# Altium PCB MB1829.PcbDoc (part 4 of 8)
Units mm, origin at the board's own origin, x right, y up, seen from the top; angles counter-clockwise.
Board outline 90 x 110 mm, 6 copper layers (Top Layer, Signal Layer 1, Signal Layer 2, Signal Layer 3, Signal Layer 4, Bottom Layer), stack 1.578 mm thick; 466 components, 354 nets, 2058 pads, 1522 vias.
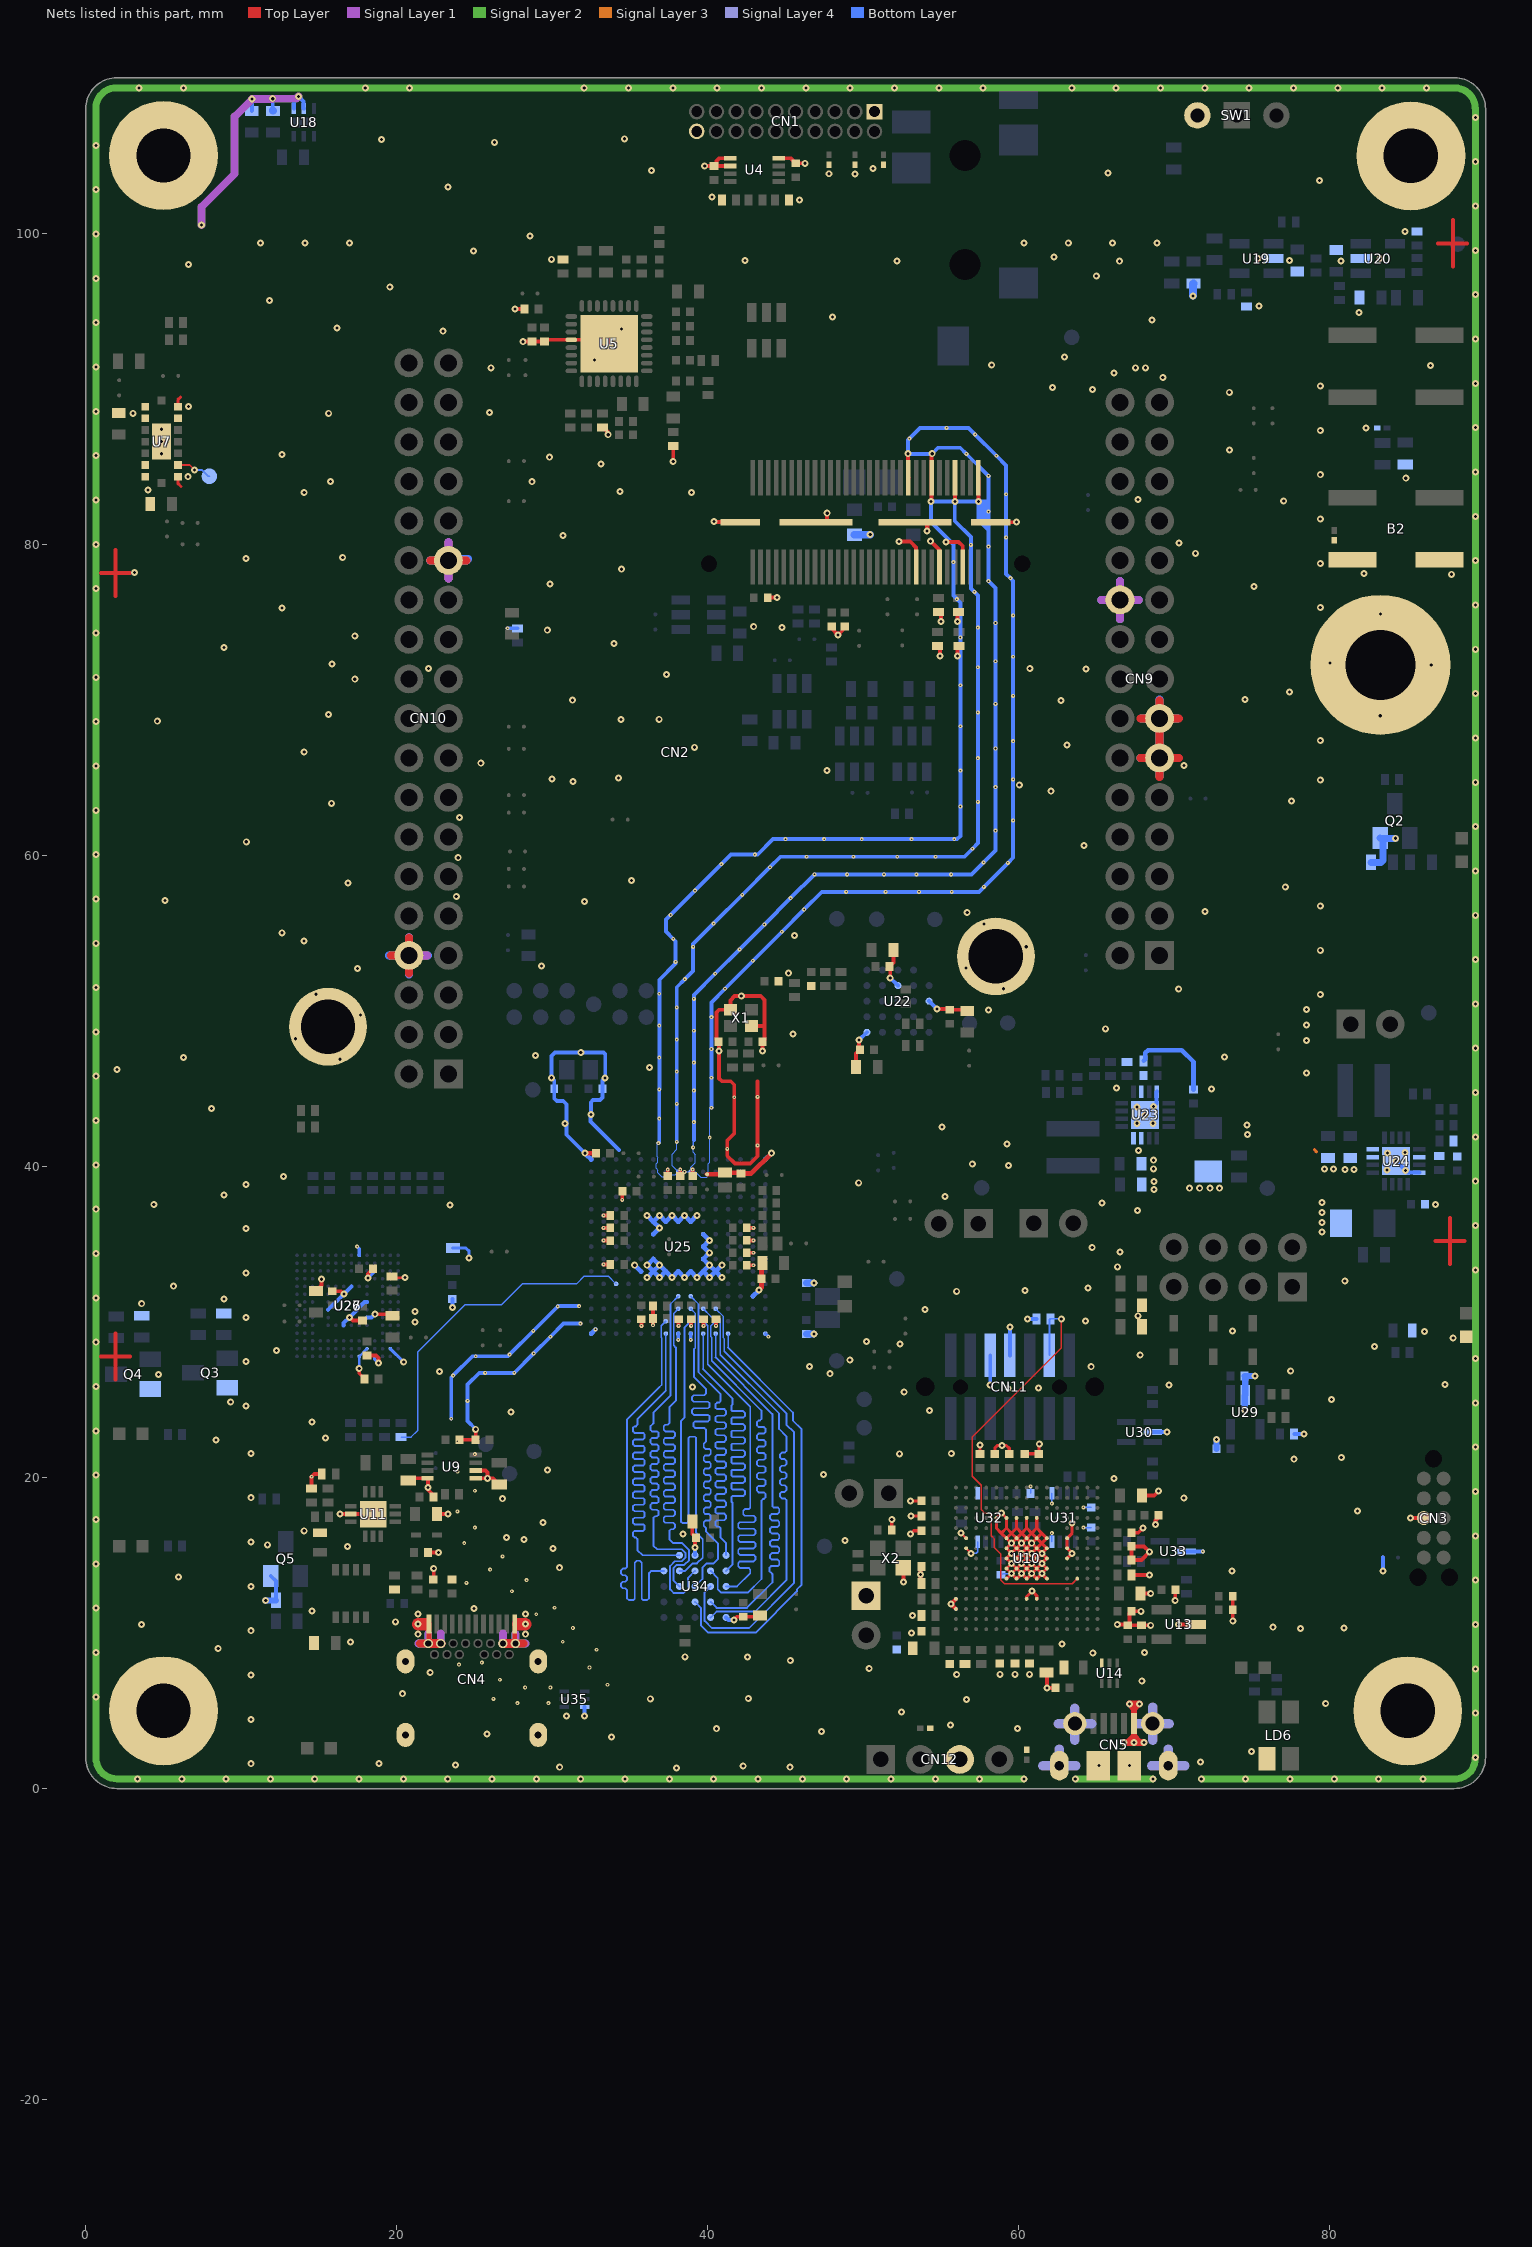
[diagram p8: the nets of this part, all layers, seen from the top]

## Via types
v1: diameter 0.45, hole 0.2, Top Layer to Bottom Layer, tented both sides, 1062 vias
v2: diameter 0.25, hole 0.1, Signal Layer 4 to Bottom Layer, tented both sides, 274 vias
v3: diameter 0.25, hole 0.1, Signal Layer 3 to Signal Layer 4, tented both sides, 119 vias
v4: diameter 0.25, hole 0.1, Top Layer to Signal Layer 1, tented both sides, 47 vias
v5: diameter 0.25, hole 0.1, Signal Layer 1 to Signal Layer 2, tented both sides, 20 vias

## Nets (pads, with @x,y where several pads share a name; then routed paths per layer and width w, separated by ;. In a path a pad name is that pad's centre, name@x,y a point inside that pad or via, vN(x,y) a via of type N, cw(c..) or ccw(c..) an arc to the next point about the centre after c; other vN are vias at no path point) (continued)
eMMC_RSTn: R111.1 U25.C11 | length 21.3
  Bottom Layer w0.1: R111.1@20.275,22.6 20.916,22.6 21.36,23.044 21.36,28.08 24.38,31.1 26.725,31.1 28.075,32.45 31.55,32.45 32.05,32.95 33.6,32.95 U25.C11@34.1,32.45
GND: B2.3 B2.4 C1.1 C2.2 C8.2 C11.1 C12.1 C18.2 C21.1 C22.1 C23.1 C24.1 C26.1 C27.1 C28.1 C29.1 C30.1 C31.1 C32.2 C33.2 C34.1 C35.1 C36.1 C37.1 C38.1 C39.1 C40.1 C42.1 C44.1 C46.1 C47.1 C49.1 C50.1 C51.1 C52.1 C53.1 C54.1 C55.1 C56.1 C57.1 C58.1 C59.1 C60.1 C61.1 C62.1 C63.1 C64.1 C65.1 C66.1 C67.1 C68.1 C69.1 C70.1 C71.1 C72.2 C73.2 C74.2 C75.2 C76.2 C77.2 C78.1 C79.1 C80.2 C81.1 C82.1 C83.2 C84.1 C85.2 C86.2 C87.2 C88.1 C89.2 C90.1 C91.2 C92.2 C93.1 C94.1 C95.1 C96.1 C97.1 C98.1 C99.1 C100.1 C101.2 C102.1 C103.1 C104.2 C105.2 C106.1 C107.2 C108.2 C109.2 C110.1 C111.1 C112.1 C113.2 C114.1 C115.1 C116.1 C117.1 C118.1 C126.1 C127.2 C128.2 C129.1 C130.1 C131.2 C132.1 C133.1 C134.1 C135.1 C136.1 C137.1 C138.1 C139.1 C140.1 C141.1 C142.1 C143.2 C144.2 C145.1 C146.1 C148.2 C149.1 CN1.1 CN1.20 CN2.1 CN2.6 CN2.7 CN2.12 CN2.13 CN2.18 CN2.19 CN2.61 CN2.62 CN2.63 CN2.64 CN2.PTH2 CN3.3 CN4.A1 CN4.A12 CN4.B1 CN4.B12 CN4.SH1 CN4.SH2 CN4.SH3 CN4.SH4 CN5.5 CN5.6 CN5.7 CN5.8 CN5.9 CN5.10 CN5.11 CN9.11 CN9.13 CN9.20 CN10.8 CN10.27 CN11.5 CN11.7 CN12.3 H1.1 H2.1 H3.1 H4.PTH1 H5.PTH1 H6.1 H7.1 JP6.1 L1.1 L5.1 LD2.2 LD6.3 Q2.2 Q3.2 Q4.2 Q5.2 R1.1 R3.1 R5.1 R12.2 R15.2 R16.2 R17.2 R18.2 R19.2 R30.1 R32.1 R35.1 R37.2 R38.1 R39.1 R46.1 R47.2 R49.1 R51.2 R53.1 R58.1 R64.1 R67.1 R71.1 R80.1 R81.1 R82.1 R91.1 R93.1 R104.1 R106.1 R108.1 R115.1 R128.1 SB30.1 SB61.1 SW1.3 U1.2 U2.2 U3.2 U4.4 U4.5 U4.6 U5.28 U5.33 U7.A1 U7.A2 U7.A6 U7.A7 U7.B4 U7.C1 U7.C6 U7.C7 U8.2 U9.4 U9.5 U9.6 U10.D5 U10.D6 U10.D7 U10.D8 U10.D9 U10.F2 U10.F6 U10.F7 U10.F8 U10.F9 U10.F10 U10.F12 U10.G2 U10.G6 U10.G7 U10.G8 U10.G9 U10.G10 U10.G12 U10.H6 U10.H7 U10.H8 U10.H9 U10.H10 U10.H12 U10.J6 U10.J7 U10.J8 U10.J9 U10.J10 U10.K6 U10.K7 U10.K8 U10.K9 U10.K10 U10.M1 U10.M8 U10.M9 U10.N1 U11.2 U11.13 U12.2 U13.2 U14.3 U15.2 U16.2 U17.2 U18.4 U18.5 U19.2 U20.2 U21.2 U22.B3 U22.C1 U22.E5 U23.6 U23.8 U23.15 U23.16 U23.17 U24.6 U24.8 U24.15 U24.16 U24.17 U25.A1 U25.A15 U25.E10 U25.F6 U25.F7 U25.F9 U25.F10 U25.G6 U25.G10 U25.H2 U25.H6 U25.H10 U25.H15 U25.J2 U25.J6 U25.J10 U25.J15 U25.K7 U25.K8 U25.K9 U25.K10 U25.L10 U25.P12 U25.R1 U25.R15 U26.A6 U26.C4 U26.E7 U26.G5 U26.H10 U26.J5 U26.K8 U26.N2 U26.N5 U26.P4 U26.P6 U27.A6 U27.C4 U27.E7 U27.G5 U27.H10 U27.J5 U27.K8 U27.N2 U27.N5 U27.P4 U27.P6 U28.2 U29.2 U30.2 U31.4 U31.5 U32.4 U32.5 U33.2 U34.C1 U34.E5 U35.3 X1.2 X1.4 X2.2 | length 1127.3
  Top Layer w0.15: R30.1@19.7,32.925 19.775,32.85 v1(20.525,32.85) ; U10.G2@56.6,15.45 v1(56.925,15.125)
  Top Layer w0.153: v1(56.275,16.425) U10.F2@56.6,16.1
  Top Layer w0.2: U7.C1@5.925,84.35 5.925,83.919 6.128,83.716 ; U7.C7@5.925,88.85 5.925,89.288 6.107,89.47 ; v1(17.585,27) 17.585,26.685 C70.1@17.933,26.338 ; v1(53.025,16.375) 53.225,16.575 C86.2@53.75,16.575 ; v1(53.025,18.5) C80.2@53.725,18.5 ; v1(53.05,17.525) C83.2@53.75,17.525 ; C75.2@57.5,21.525 v1(57.5,22.1) ; C76.2@58.45,21.525 58.45,21.9 58.6,22.05 v1(58.9,22.05) 59.205,22.05 59.375,21.88 C77.2@59.375,21.525 ; U10.K6@59.2,13.5 v1(59.525,13.825) ; U10.D7@59.85,17.4 59.85,16.75 ; C73.2@60.375,21.525 C74.2@61.275,21.525 61.293,21.543 61.293,22.133 v1(61.31,22.15) ; U10.M8@60.5,12.2 60.5,12.35 v1(60.85,12.7) 61.15,12.4 U10.M9@61.15,12.2 ; U10.D8@60.5,17.4 60.5,16.75 ; v1(60.825,15.125) U10.H9@61.15,14.8 ; U10.D9@61.15,17.4 61.15,16.75 ; U10.K10@61.8,13.5 v1(61.475,13.825) ; U10.F10@61.8,16.1 61.475,16.425 ; U10.F10@61.8,16.1 61.475,15.775 ; U10.H12@63.1,14.8 v1(63.425,15.125) U10.G12@63.1,15.45 U10.F12@63.1,16.1 63.425,16.425 v1(63.425,17.075) ; 58.875,16.425 58.55,16.75 U10.D5@58.55,17.4 v1(58.875,17.725) U10.D6@59.2,17.4 59.2,16.75 ; 58.875,16.425 U10.F6@59.2,16.1 ; 58.875,16.425 59.2,16.75 ; U10.F6@59.2,16.1 59.525,16.425 ; U10.F6@59.2,16.1 v1(59.525,15.775) ; 59.2,16.75 59.525,16.425 ; v1(59.525,13.825) U10.J7@59.85,14.15 ; v1(59.525,13.825) U10.K7@59.85,13.5 v1(60.175,13.825) ; v1(59.525,13.825) U10.J6@59.2,14.15 v1(59.525,14.475) ; v1(59.525,14.475) U10.H7@59.85,14.8 ; v1(59.525,14.475) U10.J7@59.85,14.15 ; v1(59.525,14.475) U10.H6@59.2,14.8 v1(59.525,15.125) ; v1(59.525,15.125) U10.G7@59.85,15.45 v1(60.175,15.125) ; v1(59.525,15.125) U10.G6@59.2,15.45 v1(59.525,15.775) ; v1(59.525,15.125) 59.532,15.125 59.85,14.807 U10.H7@59.85,14.8 ; v1(59.525,15.775) 59.714,15.586 U10.G7@59.85,15.45 v1(60.175,15.775) ; v1(59.525,15.775) U10.F7@59.85,16.1 ; 59.525,16.425 59.85,16.75 ; 59.525,16.425 U10.F7@59.85,16.1 ; U10.J7@59.85,14.15 v1(60.175,14.475) ; U10.J7@59.85,14.15 v1(60.175,13.825) ; U10.H7@59.85,14.8 v1(60.175,15.125) ; U10.H7@59.85,14.8 v1(60.175,14.475) ; U10.F7@59.85,16.1 60.175,16.425 ; U10.F7@59.85,16.1 59.993,15.957 v1(60.175,15.775) ; 59.85,16.75 60.175,16.425 ; v1(60.175,13.825) U10.K8@60.5,13.5 v1(60.825,13.825) ; v1(60.175,13.825) U10.J8@60.5,14.15 ; v1(60.175,14.475) U10.J8@60.5,14.15 ; v1(60.175,14.475) U10.H8@60.5,14.8 ; v1(60.175,15.125) U10.H8@60.5,14.8 ; v1(60.175,15.125) U10.G8@60.5,15.45 ; v1(60.175,15.775) U10.G8@60.5,15.45 ; v1(60.175,15.775) U10.F8@60.5,16.1 ; 60.175,16.425 60.5,16.75 ; 60.175,16.425 U10.F8@60.5,16.1 ; U10.J8@60.5,14.15 v1(60.825,14.475) ; U10.J8@60.5,14.15 v1(60.825,13.825) ; U10.H8@60.5,14.8 v1(60.825,15.125) ; U10.H8@60.5,14.8 v1(60.825,14.475) ; U10.G8@60.5,15.45 v1(60.825,15.125) ; U10.G8@60.5,15.45 v1(60.825,15.775) ; U10.F8@60.5,16.1 60.8,16.4 ; U10.F8@60.5,16.1 v1(60.825,15.775) ; 60.5,16.75 60.8,16.45 ; 60.8,16.4 60.825,16.425 ; 60.8,16.4 60.8,16.45 ; 60.8,16.45 60.825,16.425 ; v1(60.825,13.825) U10.K9@61.15,13.5 v1(61.475,13.825) ; v1(60.825,13.825) U10.J9@61.15,14.15 ; v1(60.825,14.475) U10.J9@61.15,14.15 ; v1(60.825,14.475) U10.H9@61.15,14.8 ; v1(60.825,15.125) U10.G9@61.15,15.45 ; v1(60.825,15.775) U10.G9@61.15,15.45 ; v1(60.825,15.775) U10.F9@61.15,16.1 ; 60.825,16.425 61.15,16.75 ; 60.825,16.425 U10.F9@61.15,16.1 ; U10.J9@61.15,14.15 v1(61.475,13.825) ; U10.J9@61.15,14.15 v1(61.475,14.475) ; U10.H9@61.15,14.8 v1(61.475,15.125) ; U10.H9@61.15,14.8 v1(61.475,14.475) ; U10.G9@61.15,15.45 v1(61.475,15.125) ; U10.G9@61.15,15.45 61.475,15.775 ; U10.F9@61.15,16.1 61.475,16.425 ; U10.F9@61.15,16.1 61.475,15.775 ; 61.15,16.75 61.475,16.425 ; v1(61.475,13.825) U10.J10@61.8,14.15 v1(61.475,14.475) ; v1(61.475,14.475) U10.H10@61.8,14.8 v1(61.475,15.125) ; v1(61.475,15.125) U10.G10@61.8,15.45 61.475,15.775
  Top Layer w0.25: 0.975,27.775 1.925,27.775 ; 0.975,78.15 1.925,78.15 ; 1.925,26.287 1.925,27.775 ; 1.925,29.275 1.925,27.775 ; 1.925,76.662 1.925,78.15 ; 1.925,79.65 1.925,78.15 ; 2.85,27.775 1.925,27.775 ; 2.85,78.15 1.925,78.15 ; R39.1@14.525,19.3 v4(14.525,20.05) 14.691,20.216 15.166,20.216 R38.1@15.175,20.225 ; C57.1@14.8,32 15.15,32.35 v1(15.15,32.75) ; C58.1@15.85,31.975 16.426,31.975 v1(16.6,31.801) ; v1(16.35,17.65) U11.2@17.05,17.65 U11.13@18.475,17.65 ; v1(16.95,30.3) 16.975,30.3 17.175,30.1 C66.1@17.8,30.1 ; C69.1@18.085,27.836 18.664,27.836 18.825,27.675 v1(18.825,27.375) ; v1@18.15,32.825 18.15,33.1 C55.1@18.475,33.425 ; v1(18.6,30.5) 19.625,30.5 C67.1@19.725,30.4 ; R35.1@20.725,19.8 20.875,19.95 U9.4@21.975,19.95 22,19.925 v1(22,19.35) 22,19.212 C79.1@22.35,18.862 ; C90.1@22,15.175 v1(22.675,15.175) ; C93.1@22.375,13.475 v1(22.375,14.15) ; C81.1@22.575,17.65 v1(23.3,17.65) ; C71.1@24.025,22.425 C72.2@25.075,22.425 v1(25.075,23.1) ; U9.5@25.075,19.95 v1(25.825,19.95) ; U9.6@25.075,20.45 25.7,20.45 25.825,20.325 v1(25.825,19.95) ; R37.2@26.6,19.55 26.2,19.95 v1(25.825,19.95) ; v1(27.6,95.125) C8.2@28.2,95.125 ; v1(28.122,93.025) 28.125,93.025 28.15,93.05 C12.1@29.5,93.05 ; C12.1@29.5,93.15 U5.28@31.225,93.15 33.4,93.15 34.1,93.85 v1(34.45,93.85) ; R12.2@33.225,87.5 33.32,87.5 33.558,87.263 33.558,87.084 v1(33.596,87.046) ; v4(33.3,35.25) C50.1@33.724,35.25 ; v4(33.3,36.05) C46.1@33.724,36.05 ; v4(33.3,36.85) C44.1@33.724,36.85 ; v4(33.3,33.7) C53.1@33.725,33.7 ; v4(34.5,37.85) 34.5,38.375 C42.1@34.525,38.4 ; v4(35.725,29.75) C60.1@35.725,30.175 ; v4(36.475,29.8) C65.1@36.475,31.025 ; C38.1@37.425,39.375 v4(37.425,39.8) ; v1(37.775,85.325) R15.2@37.775,86.325 ; v4(38.125,29.75) C61.1@38.125,30.175 ; C39.1@38.225,39.375 v4(38.225,39.8) ; v4(38.925,29.75) C62.1@38.925,30.175 ; C84.1@39,17.175 39,16.375 C88.1@39.25,16.125 39.175,16.05 v1(39.175,15.5) ; C40.1@39.025,39.375 v4(39.025,39.8) ; v4(39.725,29.75) C63.1@39.725,30.175 ; v1(39.8,104.325) C2.2@40.4,104.325 C2.2@40.425,104.325 ; v1(40.4,81.475) 40.454,81.475 40.496,81.433 42.054,81.433 CN2.64@42.076,81.41 ; v4(40.525,29.75) C64.1@40.525,30.175 ; U4.6@41.45,104.325 C2.2@40.425,104.325 ; U4.5@41.45,104.825 40.744,104.825 40.555,104.636 40.555,104.455 C2.2@40.425,104.325 ; v1(41.675,10.85) 41.875,11.05 C99.1@42.275,11.05 43.275,11.05 C97.1@43.35,11.125 ; C54.1@42.5,33.65 v4(42.925,33.65) ; C51.1@42.5,34.45 v4(42.925,34.45) ; C49.1@42.5,35.25 v4(42.925,35.25) ; C47.1@42.5,36.05 v4(42.925,36.05) ; X1.4@42.8,49.025 43.65,49.025 ; 43.2,45.45 v4(43.2,44.475) v4(43.2,41.35) 43.2,40.654 42.726,40.18 41.749,40.18 41.245,40.684 v4(41.245,41.125) 41.245,41.66 41.7,42.115 v4(41.7,44.45) 41.7,45.25 41.475,45.475 40.9,45.475 40.725,45.65 v1(40.725,47.425) 40.725,47.975 C32.2@40.675,48.025 40.55,48.15 40.55,49.9 40.725,50.075 X1.2@41.45,50.075 41.45,50.675 41.725,50.95 v1(42.15,50.95) 43.4,50.95 43.65,50.7 43.65,49.025 ; v1(43.525,47.425) C33.2@43.525,48.025 43.65,48.15 43.65,49.025 ; C22.1@43.85,76.571 v1(44.45,76.571) ; U4.4@44.55,104.825 45.325,104.825 45.495,104.655 45.495,104.63 45.625,104.5 C1.1@45.65,104.5 v1(46.25,104.5) ; CN2.63@46.964,81.41 47.58,81.41 47.67,81.5 47.67,81.995 v1(47.675,82) ; C23.1@47.975,74.571 v1(48.375,74.171) C24.1@48.675,74.471 ; C35.1@49.525,46.4 49.525,47.25 C34.1@49.775,47.5 49.725,47.55 v1(49.725,48.125) ; v1(51.725,52.125) 51.725,52.8 C27.1@51.675,52.85 51.925,53.1 C26.1@51.925,53.925 ; C85.2@51.825,16.625 v1(51.825,17.3) ; v1(52.3,80.175) 53.011,80.175 53.389,79.797 CN2.18@53.389,78.54 ; v1(52.575,13.275) X2.2@52.575,14.2 ; v1(52.875,85.825) 52.875,84.294 CN2.19@52.889,84.28 ; CN2.62@53.314,81.41 54.005,81.41 CN2.62@54.095,81.5 ; R49.1@53.75,13.175 53.675,13.25 v1(53.675,13.775) 53.675,14.2 C92.2@53.75,14.275 ; v1(54.325,80.2) 54.625,79.9 54.632,79.9 54.764,79.768 54.764,79.761 54.864,79.661 54.864,78.565 CN2.12@54.889,78.54 ; v1(54.35,82.75) 54.35,82.804 54.389,82.843 CN2.13@54.389,84.28 54.389,85.789 v1(54.425,85.825) ; v1(54.725,50.125) 55.5,50.125 C30.1@55.55,50.075 C31.1@56.425,50.075 ; R19.2@54.775,73.45 54.795,73.45 54.925,73.32 v1(54.925,72.825) ; R16.2@54.825,75.65 54.87,75.65 55,75.52 v1(55,75.025) ; v1(55.3,80.15) 56.125,80.15 56.389,79.886 CN2.6@56.389,78.54 ; v1@55.875,82.725 v1(55.9,82.75) 55.9,84.269 CN2.7@55.889,84.28 ; U10.N1@55.95,11.55 v1(55.625,11.875) U10.M1@55.95,12.2 ; v1(56.05,72.825) 56.05,73.375 R18.2@56.15,73.475 ; v1(56.05,75.025) 56.05,75.575 R17.2@56.125,75.65 ; CN2.1@57.389,84.28 57.4,84.269 v1(57.4,82.75) ; CN2.61@58.201,81.41 58.208,81.416 59.841,81.416 v1(59.85,81.425) ; C110.1@61.775,7.475 61.8,7.45 v1(61.8,6.475) C112.1@62.35,6.475 ; v1(66.325,10.55) 66.95,10.55 C102.1@67,10.5 ; R46.1@67.25,13.725 v1(68.4,13.725) ; C87.2@67.25,16.45 67.675,16.45 v1(67.975,16.75) ; C95.1@67.825,12.55 v1(68.475,12.55) ; v1(67.85,11.4) C101.2@67.25,11.4 67.1,11.25 67.1,10.6 C102.1@67,10.5 ; C78.1@67.9,18.85 68.7,18.85 v1(68.975,19.125) ; v1(68.475,10.5) C103.1@67.875,10.5 C102.1@67,10.5 ; v1(68.775,16.975) 68.775,17.225 68.975,17.425 C82.1@68.975,17.575 ; v1(70.05,12.1) 70.05,12.8 C96.1@70.075,12.775 ; v1(70.275,10.55) U13.2@71.375,10.55 ; v1(73.75,10.775) C100.1@73.75,11.5 C98.1@73.75,12.375 ; v1(85.175,17.395) CN3.3@86.03,17.395 ; 86.775,35.2 87.725,35.2 ; 86.95,99.35 87.9,99.35 ; 87.725,33.712 87.725,35.2 ; 87.725,36.7 87.725,35.2 ; 87.9,97.862 87.9,99.35 ; 87.9,100.85 87.9,99.35 ; 88.65,35.2 87.725,35.2 ; 88.825,99.35 87.9,99.35 ; C91.2@67.25,14.7 C89.2@67.25,15.575 68.05,15.575 v1(68.4,15.225) 67.875,14.7 C91.2@67.25,14.7
  Top Layer w0.3: CN4.B12@22.024,9.33 22.074,9.38 CN4.A1@22.074,10.58 ; CN4.A12@27.574,10.58 27.574,9.38 CN4.B1@27.624,9.33 ; v1(32.1,40.85) C36.1@32.8,40.85 ; SB30.1@39.95,39.5 41,39.5 L1.1@41.1,39.6 42.075,39.6 C37.1@42.125,39.55 42.796,39.55 44.096,40.85 v1(44.1,40.85) ; v1(43.3,32.05) 43.45,32.2 C56.1@43.45,32.775 C52.1@43.45,33.65 ; CN2.62@54.005,81.41 54.035,81.41 54.1,81.345 v1(54.1,80.85)
  Top Layer w0.4: C93.1@22.35,13.45 C93.1@22.375,13.475 ; 67,2.975 67.4,3.375 ; v1(67.4,2.975) 67.4,3.35 ; v1(67.75,5.45) v1@67.7,5.45 ; 67.775,2.975 67.4,3.35 ; 67.4,3.35 67.4,3.375 ; 67.4,3.375 CN5.5@67.4,4.175 67.4,5.15 ; 67.4,5.15 v1@67.7,5.45 ; 67.4,5.15 v1(67.1,5.45) v1@67.7,5.45
  Top Layer w0.45: v1(66.75,2.975) 67,2.975 v1(67.4,2.975) 67.775,2.975 v1(68.05,2.975)
  Top Layer w0.5: 19.635,53.564 CN10.8@20.78,53.564 ; 20.78,52.419 CN10.8@20.78,53.564 ; 20.78,54.709 CN10.8@20.78,53.564 ; 21.5,9.33 CN4.B12@22.024,9.33 ; 22.175,78.964 24.465,78.964 ; CN4.B1@27.624,9.33 28.148,9.33 ; 67.8,66.264 CN9.11@69.04,66.264 ; 67.8,68.804 CN9.13@69.04,68.804 ; 69.04,65.03 CN9.11@69.04,66.264 ; 69.04,69.95 CN9.13@69.04,68.804 ; 70.296,66.264 CN9.11@69.04,66.264 ; 70.296,68.804 CN9.13@69.04,68.804 ; CN9.11@69.04,66.264 CN9.13@69.04,68.804
  Top Layer w0.6: CN4.B12@22.024,9.33 CN4.B12@22.824,9.33 ; CN4.B1@26.824,9.33 CN4.B1@27.624,9.33
  Top Layer w0.8: v1(21.375,10.575) 21.38,10.58 21.825,10.58 ; 27.823,10.58 28.269,10.58 v1(28.273,10.575)
  Signal Layer 1 w0.5: v1(7.45,100.525) 7.45,101.698 9.575,103.823 9.575,107.5 v1(10.7,108.625) 12,108.625 v1(12.025,108.65) 13.525,108.65 v1(13.675,108.8) ; 19.604,53.564 CN10.8@20.78,53.564 ; 20.78,52.388 CN10.8@20.78,53.564 ; 20.78,54.74 CN10.8@20.78,53.564 ; 21.38,9.33 CN4.B12@22.024,9.33 22.024,9.974 ; 21.956,53.564 CN10.8@20.78,53.564 ; 22.144,78.964 CN10.27@23.32,78.964 ; CN4.B12@22.824,9.33 22.824,9.974 ; 23.32,77.788 CN10.27@23.32,78.964 ; 23.32,80.14 CN10.27@23.32,78.964 ; 24.496,78.964 CN10.27@23.32,78.964 ; CN4.B1@26.824,9.33 26.824,9.974 ; 27.624,9.974 CN4.B1@27.624,9.33 28.269,9.33 ; 65.289,76.424 CN9.20@66.5,76.424 ; 66.5,75.175 CN9.20@66.5,76.424 ; 66.5,77.635 CN9.20@66.5,76.424 ; 67.711,76.424 CN9.20@66.5,76.424 ; 67.864,66.264 CN9.11@69.05,66.264 ; 67.864,68.804 CN9.13@69.05,68.804 ; 69.05,65.06 CN9.11@69.05,66.264 ; 69.05,69.95 CN9.13@69.05,68.804 ; 70.216,66.264 CN9.11@69.05,66.264 ; 70.216,68.804 CN9.13@69.05,68.804 ; CN9.11@69.05,66.264 CN9.13@69.05,68.804
  Signal Layer 1 w0.6: CN4.B12@22.024,9.33 CN4.B12@22.824,9.33 ; CN4.B1@26.824,9.33 CN4.B1@27.624,9.33
  Signal Layer 2 w0.45: 0.65,1.962 v1(0.65,5.9) v1(0.65,8.75) v1(0.65,11.6) v1(0.65,14.45) v1(0.65,17.3) v1(0.65,20.15) v1(0.65,23) v1(0.65,25.85) v1(0.65,28.7) 0.65,31.05 v1(0.65,77.15) v1(0.65,80) v1(0.65,105.65) 0.65,107.975 0.649,108.025 cw(c1.973,108.026) 1.973,109.35 v1(3.425,109.35) v1(6.275,109.35) v1(17.975,109.35) v1(20.825,109.35) v1(32.05,109.35) v1(34.9,109.35) v1(37.75,109.35) v1(40.6,109.35) v1(43.45,109.35) v1(46.3,109.35) v1(49.15,109.35) v1(52,109.35) v1(54.85,109.35) v1(57.7,109.35) v1(63.4,109.35) v1(66.25,109.35) v1(69.1,109.35) v1(71.95,109.35) v1(74.8,109.35) v1(77.65,109.35) v1(80.5,109.35) v1(83.35,109.35) v1(86.2,109.35) 88.038,109.35 ; 0.662,1.962 ccw(c2,1.962) 2,0.625 v1(3.325,0.625) v1(6.175,0.625) v1(9.025,0.625) v1(11.875,0.625) v1(14.725,0.625) v1(17.575,0.625) v1(20.425,0.625) v1(23.275,0.625) v1(26.125,0.625) v1(28.975,0.625) v1(31.825,0.625) v1(34.675,0.625) v1(37.525,0.625) v1(40.375,0.625) v1(43.225,0.625) v1(46.075,0.625) v1(48.925,0.625) v1(51.775,0.625) v1(54.625,0.625) v1(57.475,0.625) v1(60.325,0.625) ; CN5.9@62.6,1.155 CN5.9@62.6,1.475 ; v1(63.625,0.625) 65.282,0.625 66.968,0.625 v1(68.625,0.625) ; v1(71.725,0.625) v1(74.575,0.625) v1(77.425,0.625) v1(80.275,0.625) v1(83.125,0.625) v1(85.975,0.625) 88.135,0.625 88.401,0.678 88.651,0.781 88.877,0.932 89.042,1.097 ccw(c87.925,1.962) 89.052,1.11 ccw(c87.925,1.962) v1@89.338,1.962 ; 88.038,109.338 cw(c88.038,108.038) 89.338,108.038 ; v1(89.35,2) v1(89.35,4.85) v1(89.35,27.65) v1(89.35,33.35) v1(89.35,78.95) v1(89.35,81.8) v1(89.35,84.65) v1(89.35,87.5) v1(89.35,90.35) v1(89.35,93.2) v1(89.35,96.05) v1(89.35,98.9) v1(89.35,101.75) v1(89.35,104.6) v1(89.35,107.45) 89.35,108.038
  Signal Layer 3 w0.2: 79,41.073 79.125,40.948
  Signal Layer 3 w0.5: 20.78,52.409 CN10.8@20.78,53.564 ; 20.78,54.719 CN10.8@20.78,53.564 ; 21.935,53.564 CN10.8@20.78,53.564 ; 22.165,78.964 CN10.27@23.32,78.964 ; 23.32,77.809 CN10.27@23.32,78.964 ; 23.32,80.119 CN10.27@23.32,78.964 ; 24.475,78.964 CN10.27@23.32,78.964 ; 67.885,66.264 CN9.11@69.04,66.264 ; 67.885,68.804 CN9.13@69.04,68.804 ; 69.04,65.09 CN9.11@69.04,66.264 ; 69.04,69.959 CN9.13@69.04,68.804 ; 70.195,66.264 CN9.11@69.04,66.264 ; 70.195,68.804 CN9.13@69.04,68.804 ; CN9.11@69.04,66.264 CN9.13@69.04,68.804
  Signal Layer 4 w0.5: 19.606,53.564 CN10.8@20.78,53.564 ; 20.78,52.39 CN10.8@20.78,53.564 ; 20.78,54.738 CN10.8@20.78,53.564 ; 21.455,9.33 CN4.B12@22.024,9.33 22.024,9.899 ; 21.954,53.564 CN10.8@20.78,53.564 ; 22.146,78.964 CN10.27@23.32,78.964 ; CN4.B12@22.824,9.33 22.824,9.899 ; 23.32,77.79 CN10.27@23.32,78.964 ; 23.32,80.138 CN10.27@23.32,78.964 ; 24.494,78.964 CN10.27@23.32,78.964 ; CN4.B1@26.824,9.33 26.824,9.899 ; 27.624,9.899 CN4.B1@27.624,9.33 28.193,9.33 ; 65.289,76.424 CN9.20@66.5,76.424 ; 66.5,75.2 CN9.20@66.5,76.424 ; 66.5,77.635 CN9.20@66.5,76.424 ; 67.711,76.424 CN9.20@66.5,76.424 ; 67.801,66.264 CN9.11@68.975,66.264 ; 67.866,68.804 CN9.13@69.04,68.804 ; 69.04,65.09 CN9.11@69.04,66.264 ; 69.04,69.95 CN9.13@69.04,68.804 ; 70.214,66.264 CN9.11@69.04,66.264 ; 70.214,68.804 CN9.13@69.04,68.804 ; CN9.11@69.04,66.264 CN9.13@69.04,68.804
  Signal Layer 4 w0.6: CN4.B12@22.024,9.33 CN4.B12@22.824,9.33 ; CN4.B1@26.824,9.33 CN4.B1@27.624,9.33 ; 61.525,1.475 CN5.9@62.6,1.475 ; 62.525,4.175 CN5.6@63.6,4.175 ; 62.6,2.55 CN5.9@62.6,1.475 ; 63.6,3.1 CN5.6@63.6,4.175 ; 63.6,5.175 CN5.6@63.6,4.175 ; 63.675,1.475 CN5.9@62.6,1.475 ; 64.675,4.175 CN5.6@63.6,4.175 ; 67.525,4.175 CN5.7@68.6,4.175 ; 68.525,1.475 CN5.8@69.6,1.475 ; 68.6,3.1 CN5.7@68.6,4.175 ; 68.6,5.25 CN5.7@68.6,4.175 ; 69.6,2.55 CN5.8@69.6,1.475 ; 69.675,4.175 CN5.7@68.6,4.175 ; 70.675,1.475 CN5.8@69.6,1.475
  Bottom Layer w0.08: v2@36.75,41.425 36.75,40.61 36.79,40.57 36.79,40.281 36.69,40.181 36.69,39.87 36.79,39.77 36.79,39.585 37.05,39.325 37.565,39.325 37.695,39.455 37.905,39.455 U25.H2@38.1,39.65 ; v2(38,41.575) 38,41.1 37.7,40.8 37.7,40.05 U25.H2@38.1,39.65 ; U25.J2@38.9,39.65 38.9,39.935 39.19,40.225 39.19,40.76 39.05,40.9 v2(39.05,41.225) ; v2@40.125,43.775 v2(40.125,41.85) 40.125,40.275 40.035,40.185 40.035,39.425 39.925,39.315 39.79,39.315 39.775,39.3 39.54,39.3 39.19,39.65 U25.H2@38.1,39.65
  Bottom Layer w0.1: v2(39.05,41.225) 39.05,41.625 39.125,41.7 ; v1(56.925,15.125) 57.25,15.125 57.35,15.225 U32.4@57.35,15.875 ; C146.1@58.875,13.725 58.975,13.825 v1(59.525,13.825) ; C143.2@60.75,18.975 v2(60.75,19.425) ; U31.4@62.125,15.875 v2(62.125,16.425) ; v2(62.125,18.325) U31.5@62.125,18.975 ; v2(64.15,16.775) C145.1@64.65,16.775 ; v2(64.15,18.075) C144.2@64.65,18.075
  Bottom Layer w0.15: v1(17.585,27) U27.P6@17.585,27.786 U27.N5@18.085,28.286
  Bottom Layer w0.2: v2(17.45,34.85) 17.585,34.715 U27.A6@17.585,34.286 ; U27.N2@19.585,28.286 v1(20.448,27.423) ; C137.1@23.575,34.75 C137.1@23.625,34.75 24.45,34.75 24.65,34.55 v1(24.65,34.125) ; U25.R15@43.7,29.25 v2@43.875,29.075
  Bottom Layer w0.25: C114.1@10.675,107.869 10.7,107.894 v1(10.7,108.625) ; Q5.2@11.9,13.675 12.225,13.35 R128.1@12.225,12.1 ; C113.2@12.025,107.894 v1(12.025,108.65) ; U18.4@13.375,108.015 13.385,108.025 13.385,108.51 v1(13.675,108.8) 14.015,108.46 14.015,108.025 U18.5@14.025,108.015 ; U27.H10@15.585,30.786 v1(16.6,31.801) U27.E7@17.085,32.286 ; U27.K8@16.585,29.786 16.585,29.935 v1(16.95,30.3) 17.936,31.286 U27.G5@18.085,31.286 ; U27.J5@18.085,30.286 18.386,30.286 v1(18.6,30.5) ; v1@18.15,32.825 18.15,32.851 U27.C4@18.585,33.286 ; U27.P4@18.585,27.786 18.585,27.615 v1(18.825,27.375) ; v2(23.5,23.775) 23.5,26.425 v2(23.625,26.55) 24.875,27.8 v2(25.075,27.8) 27.15,27.8 v2(27.25,27.9) v2(28.775,29.425) v2(30.35,31) 30.375,31.025 v2(31.725,31.025) ; v1(23.575,30.925) C139.1@23.575,31.475 ; v1(25.075,23.1) 24.55,23.625 v2(24.55,24.925) 24.55,25.975 25.3,26.725 v2(25.675,26.725) v2(27.55,26.725) v2(28.8,27.975) v2(29.875,29.05) 30.725,29.9 v2(31.8,29.9) ; v2(27.125,74.6) R71.1@27.75,74.6 ; 30.9,42.038 30.9,44 30.7,44.2 30.3,44.2 30.125,44.375 30.125,45.525 v1(29.95,45.7) 29.95,47.095 30.18,47.325 v1(31.829,47.325) 33.3,47.325 33.4,47.225 33.4,45.7 v1(33.375,45.675) 33.225,45.525 33.225,44.425 33.069,44.269 32.619,44.269 32.475,44.125 v1(32.475,43.35) 32.464,43.339 32.464,42.886 34.287,41.063 ; 30.913,42.038 v1(32.1,40.85) v1@32.225,40.725 ; v1(32.075,4.675) U35.3@32.075,5.25 ; v2(36.825,41.5) 36.875,41.55 v2(36.875,43.075) v2(36.875,44.95) 36.885,44.96 36.885,52.004 37.927,53.046 v2(37.927,53.148) 37.927,54.476 v2(37.775,54.629) 37.309,55.095 37.309,55.875 v2(37.603,56.168) v2(39.173,57.738) v2(40.872,59.438) 41.486,60.051 v2(43.025,60.051) 43.209,60.051 44.199,61.041 v2(44.991,61.041) v2(47.476,61.041) v2(49.893,61.041) v2(53.101,61.041) v2(55.845,61.041) 56.022,61.041 56.235,61.254 v2(56.235,63.142) v2(56.235,65.449) v2(56.235,68.303) v2(56.235,70.938) v2(56.235,74.01) 56.235,76.246 55.783,76.698 v2(55.783,78.86) 55.783,79.993 54.35,81.426 v1(54.35,82.75) v1(55.9,82.75) ; v2(38,41.575) v2(38,44.025) v2(38,46.1) v2(38,48.15) v2(38,50.225) 38,51.521 v2(38.529,52.05) 39.057,52.578 v2(39.057,54.116) 39.057,54.302 v2(40.373,55.618) v2(42.211,57.456) v2(43.996,59.24) 44.667,59.911 v2(46.353,59.911) v2(49.359,59.911) v2(52.176,59.911) v2(54.639,59.911) 56.49,59.911 v2(57.004,60.425) 57.365,60.786 v2(57.365,63.436) v2(57.365,66.254) v2(57.365,69.197) v2(57.365,72.098) v2(57.365,74.644) 57.365,76.714 56.913,77.166 v2(56.913,79.966) 56.913,80.461 55.875,81.499 55.875,82.725 v1(55.9,82.75) ; v2(38.1,28.85) U25.H15@38.1,29.25 ; v2(38.9,28.85) U25.J15@38.9,29.25 ; 39.1,41.7 v2(39.1,42.85) v2(39.1,44.875) v2(39.1,46.675) v2(39.1,48.725) v2(39.1,50.775) 39.1,51.023 v2(40.468,52.391) v2(42.037,53.96) v2(43.634,55.557) v2(45.325,57.249) v2(46.858,58.781) v2(48.954,58.781) v2(51.327,58.781) v2(53.411,58.781) v2(55.64,58.781) 56.958,58.781 v2(57.727,59.55) 58.495,60.318 v2(58.495,61.588) v2(58.495,64.394) v2(58.495,66.871) v2(58.495,69.739) v2(58.495,72.484) v2(58.495,74.94) 58.495,77.182 v2(58.043,77.634) v2(58.043,79.852) 58.043,80.929 ; U34.C1@39.175,15 v1(39.175,15.5) ; v2(40.225,43.775) v2(40.225,45.7) v2(40.225,47.55) v2(40.225,49.6) 40.225,50.55 v2(41.103,51.428) v2(42.9,53.225) v2(44.765,55.09) v2(46.194,56.519) 47.326,57.651 v2(48.886,57.651) v2(51.43,57.651) v2(53.576,57.651) v2(55.681,57.651) 57.426,57.651 v2(57.748,57.973) v2(59.296,59.521) 59.625,59.85 v2(59.625,62.248) v2(59.625,64.89) v2(59.625,67.346) v2(59.625,70.255) v2(59.625,72.773) v2(59.625,75.435) 59.625,77.65 v2(59.452,77.823) 59.173,78.102 v2(59.173,80.45) v2(59.173,83.215) 59.173,85.078 v2(58.554,85.696) v2(57.182,87.069) 56.761,87.49 v2(55.351,87.49) 53.652,87.49 v2(52.963,86.801) 52.875,86.713 v1(52.875,85.825) 52.9,85.8 54.4,85.8 v1(54.425,85.825) 54.81,86.21 56.231,86.21 v2(56.628,85.813) 56.777,85.663 v2(58.043,84.398) 58.043,82.735 ; U34.E5@41.175,11 41.325,10.85 v1(41.675,10.85) ; v1(49.725,48.125) U22.E5@50.225,48.625 ; v1(51.725,52.125) U22.B3@52.225,51.625 ; U22.C1@54.225,50.625 v1(54.725,50.125) ; v1@55.289,80.161 v1(55.3,80.15) ; v1(58.155,25.945) CN11.5@58.155,27.857 ; CN11.7@59.425,27.857 v1(59.425,29.675) ; v1(60.55,30.2) R108.1@61.125,30.2 ; v1(68.122,43.314) 68.849,44.041 68.849,44.791 U23.8@68.872,44.814 ; U30.2@68.6,22.925 v1(69.525,22.925) ; U33.2@70.775,15.25 v2(71.825,15.25) ; R115.1@77.7,22.8 v1(78.325,22.8) ; v1(83.4,14) SB61.1@83.4,14.85 ; v1(84.25,40.35) v1(84.85,39.75) 84.977,39.623 85.727,39.623 U24.8@85.75,39.6 ; v1(55.9,82.75) v1(57.4,82.75) ; v1@57.4,82.729 57.4,81.572 58.043,80.929 ; v1@57.4,82.729 v1(57.4,82.75) ; v1@57.4,82.729 57.625,82.504 57.625,81.668 58.043,81.25 ; v1(57.4,82.75) 57.714,82.75 ; 57.714,82.75 57.714,81.864 57.871,81.707 ; 57.714,82.75 57.871,82.75 ; 57.871,81.707 57.871,82.75 ; 57.871,81.707 58.043,81.535 ; 57.871,82.75 58.028,82.75 58.043,82.735 ; 58.043,80.929 58.043,81.25 ; 58.043,81.25 58.043,81.535 ; 58.043,81.535 v2(58.043,82.101) 58.043,82.735
  Bottom Layer w0.3: v1@32.225,40.725 U25.A1@32.5,40.45 ; U25.A15@32.5,29.25 v2(32.775,29.525) ; v1(35.3,33.65) U25.E10@35.7,33.25 ; v1(36.1,32.85) U25.F10@36.5,33.25 ; v1(36.1,36.85) U25.F6@36.5,36.45 ; U25.F7@36.5,35.65 v1(36.9,36.05) U25.F6@36.5,36.45 ; v1(39.3,36.85) U25.J6@38.9,36.45 38.5,36.85 U25.H6@38.1,36.45 v1(37.7,36.85) U25.G6@37.3,36.45 v1(36.9,36.85) U25.F6@36.5,36.45 ; U25.K7@39.7,35.65 v1(40.1,35.25) U25.K8@39.7,34.85 v1(40.1,34.45) U25.K9@39.7,34.05 v1(40.1,33.65) ; v1(40.9,32.85) U25.L10@40.5,33.25 ; v1(40.9,33.65) U25.L10@40.5,33.25 ; v1(43.3,32.05) U25.P12@42.9,31.65 v1(43.3,32.05) ; U25.R1@43.7,40.45 v1(44.1,40.85) ; R81.1@68.022,46.791 68.127,46.896 68.127,47.299 68.303,47.475 70.475,47.475 71.225,46.725 C130.1@71.225,44.95 ; U25.F10@36.5,33.25 v1(36.1,33.65) U25.F9@36.5,34.05 v1(36.9,33.65) ; U25.F10@36.5,33.25 v1(36.9,33.65) ; U25.F10@36.5,33.25 v1(36.9,32.85) U25.G10@37.3,33.25 ; v1(36.9,33.65) U25.G10@37.3,33.25 ; U25.G10@37.3,33.25 v1(37.7,32.85) U25.H10@38.1,33.25 v1(38.5,32.85) U25.J10@38.9,33.25 v1(39.3,32.85) U25.K10@39.7,33.25 ; U25.K10@39.7,33.25 v1(40.1,32.85) U25.L10@40.5,33.25 ; U25.K10@39.7,33.25 v1(40.1,33.65) ; v1(40.1,33.65) U25.L10@40.5,33.25
  Bottom Layer w0.4: v1(11.575,12.1) R128.1@12.225,12.1 ; C142.1@72.7,21.85 v1(72.7,22.45) ; v1(74.525,24.3) 74.525,25.275 U29.2@74.55,25.3 74.55,26.475 C141.1@74.5,26.525 v1(75.175,26.525)
  Bottom Layer w0.45: C140.1@46.334,29.231 v1(46.83,29.231) ; C138.1@46.342,32.517 v1(46.83,32.517) ; R80.1@82.65,59.55 83.268,59.55 83.4,59.682 83.4,60.95 Q2.2@83.25,61.1 ; Q2.2@83.225,61.125 Q2.2@83.25,61.1 ; v1(84.2,61.1) Q2.2@83.25,61.1
  Bottom Layer w0.5: C113.2@12.025,107.894 C113.2@12.05,107.869 ; 19.49,53.564 CN10.8@20.78,53.564 ; 20.78,52.349 CN10.8@20.78,53.564 ; 22,53.564 CN10.8@20.78,53.564 ; CN10.27@23.39,79.058 24.6,79.058 ; L5.1@49.425,80.621 v1(50.439,80.621) ; 65.289,76.424 CN9.20@66.5,76.424 ; 66.5,75.175 CN9.20@66.5,76.424 ; 66.5,77.635 CN9.20@66.5,76.424 ; 67.711,76.424 CN9.20@66.5,76.424 ; 67.829,66.264 CN9.11@69.04,66.264 ; 67.829,68.804 CN9.13@69.04,68.804 ; 69.04,70.015 CN9.13@69.04,68.804 ; 70.251,66.264 CN9.11@69.04,66.264 ; 70.251,68.804 CN9.13@69.04,68.804 ; v1(71.2,95.975) 71.2,96.75 C117.1@71.225,96.775 ; CN9.11@69.04,66.264 CN9.13@69.04,68.804
  other v1: 37.975,1.325 30.475,1.375 45.275,1.375 42.275,1.45 65.15,1.475 67.1,1.475 23.775,1.525 10.625,1.6 18.85,1.625 71.675,1.7 74.95,2.388 33.8,3.325 25.8,3.5 47.3,3.675 40.55,3.85 59.9,3.875 55.6,4.1 10.625,4.45 30.9,4.675 52.45,4.925 79.725,5.475 56.625,5.725 36.3,5.775 42.6,5.8 20.375,6.1 67.9,6.925 10.625,7.3 56,7.325 58.775,7.35 59.75,7.35 60.675,7.35 22.15,7.475 89.35,7.7 50.375,7.725 45.3,8.225 42.55,8.45 38.525,8.475 64.75,8.725 68.075,8.75 8.521,9 62.775,9.3 17.025,9.425 21.375,9.925 28.273,9.925 53.1,10 10.625,10.15 78.1,10.3 80.9,10.325 76.325,10.375 3.575,10.55 89.35,10.55 19.925,10.725 53.15,11.125 21.375,11.225 28.273,11.225 14.55,11.425 24.975,11.575 10.625,13 89.35,13.4 5.975,13.6 73.7,14 30.45,14.2 30.05,15.425 16.825,15.575 11.7,15.675 10.625,15.85 48.825,15.95 28.175,16.025 27.05,16.15 89.35,16.25 38.4,16.375 14.05,16.575 29.4,17.1 81.775,17.85 26.8,18.635 70.6,18.675 10.625,18.7 89.35,19.1 66.105,19.925 47.425,20.2 29.7,20.475 77.675,21.175 80.725,21.275 52.325,21.525 10.625,21.55 55.65,21.55 89.35,21.95 8.375,22.4 15.425,22.55 14.55,23.575 27.35,24.2 54.25,24.3 10.3,24.6 89.35,24.8 9.325,24.85 80.1,25.025 52.625,25.5 59.3,25.725 61.25,25.75 39.025,25.81 69.65,25.95 87.4,25.975 4.675,26.625 47.85,26.675 22.75,26.825 77.475,26.85 64.65,27.125 46.525,27.15 10.3,27.45 49.125,27.55 67.8,27.875 12.275,28.175 82.85,28.425 52.35,28.575 50.205,28.745 87.925,28.975 86.075,29.4 73.725,29.425 21.175,30 64.275,30.075 10.3,30.3 67.657,30.4 21.175,30.675 53.95,30.8 3.6,31.175 8.9,31.475 0.65,31.55 56,31.975 60.4,32.025 64.45,32.175 5.65,32.3 80.95,32.625 18.145,32.825 10.3,33.15 66.35,33.55 0.65,34.4 66.49,34.505 64.713,34.8 79.475,35.79 10.3,36 89.35,36.2 79.475,36.384 38.5,36.85 79.475,37.029 67.625,37.175 0.65,37.25 23.425,37.525 4.375,37.55 86.775,37.55 65.35,37.65 79.475,37.674 55.25,38.075 8.9,38.175 68.675,38.525 70.98,38.6 71.625,38.6 72.275,38.6 72.9,38.6 10.3,38.85 49.7,38.95 68.675,39.025 89.35,39.05 12.725,39.35 83.675,39.775 80.975,39.8 81.55,39.8 79.65,39.825 80.225,39.825 68.65,39.85 59.325,40.05 0.65,40.1 57,40.15 68.65,40.4 83.7,40.875 84.825,40.9 67.7,41.025 59.245,41.445 89.35,41.9 74.7,42.05 55.046,42.54 74.675,42.675 30.825,42.75 67.6,42.775 68.625,42.775 0.65,42.95 8.1,43.725 67.6,43.825 68.65,43.85 89.35,44.75 72.375,44.975 66.275,45.05 0.65,45.8 78.5,46 2,46.225 36.25,46.35 16.348,46.889 6.275,47 73.225,47.025 28.925,47.125 89.35,47.6 78.5,48.1 13.489,48.21 45.475,48.515 0.65,48.65 65.575,48.85 78.5,49.1 17.669,49.748 58.05,50.05 78.5,50.1 89.35,50.45 79.375,51.05 14.81,51.069 70.275,51.4 59,51.425 0.65,51.5 45.175,52.425 17.475,52.725 56.6,52.75 29.3,52.9 89.35,53.3 79.375,53.9 60.475,54.125 0.65,54.35 14.025,54.5 45.567,54.839 12.625,55.025 57.75,55.6 89.35,56.15 56.675,56.325 71.975,56.4 79.375,56.75 32.075,57.025 5.1,57.1 0.65,57.2 23.825,57.35 77.125,57.975 16.875,58.225 35.1,58.375 89.35,59 23.95,59.85 0.65,60.05 64.175,60.625 10.325,60.875 89.35,61.85 24.025,62.425 0.65,62.9 15.8,63.35 77.525,63.5 62.075,64.125 60.025,64.525 89.35,64.7 31.325,64.75 79.375,64.85 29.975,64.9 34.25,64.975 47.65,65.45 0.65,65.75 70.625,65.775 25.4,65.925 14.05,66.65 39.15,66.95 63.1,67.1 79.375,67.375 89.35,67.55 0.65,68.6 4.6,68.625 34.425,68.725 36.875,68.75 83.232,68.98 15.6,69.05 62.7,69.95 31.3,69.975 74.525,70.019 89.35,70.4 77.395,70.5 17.3,71.325 0.65,71.45 37.35,71.625 64.325,71.975 22.03,72.015 60.7,72.025 86.514,72.243 15.825,72.3 80.002,72.359 89.35,73.25 8.895,73.364 33.975,73.625 17.3,74.1 0.65,74.3 29.675,74.475 44.775,74.65 42.95,74.7 83.25,75.525 12.625,75.9 79.375,75.925 89.35,76.1 75.125,77.275 29.85,77.45 87.825,78.075 82.175,78.125 3.125,78.2 34.45,78.4 79.375,78.775 10.3,79.1 16.525,79.15 71.35,79.425 70.3,80.075 30.675,80.575 79.375,81.625 77.025,82.775 0.65,82.85 67.65,82.875 14.05,83.325 38.95,83.325 34.358,83.4 4.015,83.5 28.7,84.025 15.75,84.05 84.874,84.25 6.575,84.346 79.375,84.475 33.142,85.167 29.825,85.6 0.65,85.7 12.625,85.775 4.875,85.825 73.55,86.075 4.875,86.6 79.375,87.325 4.875,87.4 82.325,87.475 3.05,88.425 15.625,88.425 25.95,88.475 0.65,88.55 6.603,88.871 73.525,89.775 64.725,89.95 62.15,90.075 79.375,90.175 69.25,90.725 66.125,91.025 26.05,91.35 67.5,91.35 68.15,91.35 0.65,91.4 86.475,91.5 58.25,91.525 32.7,91.85 62.925,92.05 22.975,93.7 16.15,93.9 0.65,94.25 68.55,94.425 48.025,94.625 81.861,94.9 75.425,95.325 11.825,95.675 19.55,96.55 0.65,97.1 64.975,97.25 6.6,98 66.475,98.2 52.15,98.225 80.7,98.225 42.4,98.25 77.4,98.25 29.95,98.325 75.375,98.375 83.2,98.375 62.25,98.475 24.925,98.85 11.25,99.375 14.1,99.375 16.95,99.375 60.325,99.375 63.175,99.375 66.025,99.375 68.875,99.375 28.575,99.825 0.65,99.95 84.814,100.1 45.9,102.125 40.275,102.325 0.65,102.8 23.3,102.975 79.325,103.4 49.45,103.8 47.8,103.825 65.725,103.875 36.375,104.025 50.625,104.175 26.275,105.85 19.025,106.025 34.65,106.075
  other v2: 27.75,5.5 29.75,5.5 26.21,5.77 28.25,6.5 29.875,6.5 33.55,6.675 24.905,6.995 26.625,7 32.39,7.785 24,7.975 25.475,8.1 32.85,8.925 30.67,9.44 31.325,10.325 28.97,11.21 30.15,11.625 27.405,12.69 24.475,13.225 28.35,13.4 26.005,14.075 26.8,14.925 24.34,15.785 25.025,16.775 23.9,17.825 25.025,19.15 23.9,20.375 25.025,21.5 23.9,22.325 43.897,29.05 38.5,39.65 36.875,47 36.875,49.05 36.875,51.1 56.009,76.472 57.139,76.94
GNDDetect: CN11.11 R108.2 U10.K13 | length 28.3
  Top Layer w0.1: v1(62.725,30.2) 62.725,28.325 57,22.6 57,20.075 57.575,19.5 57.575,17.947 57.822,17.7 58.15,17.7 58.225,17.625 58.225,16.25 58.425,16.05 58.425,15.487 58.835,15.077 58.835,13.41 59.07,13.175 63.425,13.175 U10.K13@63.75,13.5
  Bottom Layer w0.1: R108.2@62.025,30.2 v1(62.725,30.2)
  Bottom Layer w0.12: CN11.11@61.965,27.857 61.965,30.14 R108.2@62.025,30.2
GPIO2: TP3.1 U7.C2 | length 2.3
  Top Layer w0.12: U7.C2@5.925,85.1 6.675,85.1 v1(7,84.775)
  Bottom Layer w0.12: v1(7,84.775) 7.488,84.775 7.888,84.375 TP3.1@7.95,84.375
HEXASPI1.CLK: U25.J14 U34.B2 | length 29.4
  Bottom Layer w0.12: U34.B2@38.175,14 38.55,14 39.025,14.475 39.3,14.475 39.675,14.85 39.675,16.025 39.25,16.45 39.25,22.55 39.175,22.625 38.85,22.625 38.75,22.525 38.75,17.175 38.65,17.075 38.35,17.075 38.275,17.15 38.275,23.65 38.5,23.875 38.5,29.65 U25.J14@38.9,30.05
HEXASPI1.DQS0: U25.J13 U34.C3 | length 29
  Bottom Layer w0.1: U25.J13@38.9,30.85 39.2,30.55 39.2,28.35 39.1,28.25
  Bottom Layer w0.12: 39.1,28.25 39.1,26.475 39.875,25.7 39.875,25.5 39.875,25.395 39.77,25.29 39.09,25.29 38.985,25.185 38.985,24.975 39.09,24.87 39.875,24.87 40.01,24.87 40.115,24.765 40.115,24.555 40.01,24.45 39.875,24.45 39.09,24.45 38.985,24.345 38.985,24.135 39.09,24.03 39.875,24.03 40.01,24.03 40.115,23.925 40.115,23.715 40.01,23.61 39.875,23.61 39.179,23.61 39.074,23.505 39.074,23.295 39.179,23.19 39.77,23.19 39.875,23.085 39.875,22.9 39.875,22.475 39.875,22.3 39.84,22.265 39.735,22.16 39.735,21.95 39.84,21.845 39.875,21.845 40.085,21.845 40.19,21.74 40.19,21.53 40.085,21.425 39.875,21.425 39.84,21.425 39.735,21.32 39.735,21.11 39.84,21.005 39.875,21.005 40.085,21.005 40.19,20.9 40.19,20.69 40.085,20.585 39.875,20.585 39.84,20.585 39.735,20.48 39.735,20.27 39.84,20.165 39.875,20.165 40.085,20.165 40.19,20.06 40.19,19.85 40.085,19.745 39.875,19.745 39.84,19.745 39.735,19.64 39.735,19.43 39.84,19.325 39.875,19.325 40.085,19.325 40.19,19.22 40.19,19.01 40.085,18.905 39.875,18.905 39.84,18.905 39.735,18.8 39.735,18.59 39.84,18.485 39.875,18.485 40.085,18.485 40.19,18.38 40.19,18.17 40.085,18.065 39.875,18.065 39.84,18.065 39.735,17.96 39.735,17.75 39.84,17.645 39.875,17.645 40.085,17.645 40.19,17.54 40.19,17.33 40.085,17.225 39.875,17.225 39.84,17.225 39.735,17.12 39.735,16.91 39.84,16.805 39.875,16.77 39.875,16.725 39.875,16.55 40.65,15.775 40.65,14.75 40.375,14.475 39.925,14.475 39.65,14.2 39.65,13.475 U34.C3@39.175,13
HEXASPI1.DQS1: U25.H13 U34.B3 | length 29.6
  Bottom Layer w0.1: 37.95,28.35 37.8,28.5 37.8,30.55 U25.H13@38.1,30.85
  Bottom Layer w0.12: 37.81,28.5 37.81,28.49 37.95,28.35 37.95,24.95 37.525,24.525 37.525,23.6 37.525,23.495 37.42,23.39 37.268,23.39 37.163,23.285 37.163,23.075 37.268,22.97 37.525,22.97 37.782,22.97 37.887,22.865 37.887,22.655 37.782,22.55 37.525,22.55 37.268,22.55 37.163,22.445 37.163,22.235 37.268,22.13 37.525,22.13 37.782,22.13 37.887,22.025 37.887,21.815 37.782,21.71 37.525,21.71 37.268,21.71 37.163,21.605 37.163,21.395 37.268,21.29 37.525,21.29 37.782,21.29 37.887,21.185 37.887,20.975 37.782,20.87 37.525,20.87 37.268,20.87 37.163,20.765 37.163,20.555 37.268,20.45 37.525,20.45 37.782,20.45 37.887,20.345 37.887,20.135 37.782,20.03 37.525,20.03 37.268,20.03 37.163,19.925 37.163,19.715 37.268,19.61 37.525,19.61 37.782,19.61 37.887,19.505 37.887,19.295 37.782,19.19 37.525,19.19 37.268,19.19 37.163,19.085 37.163,18.875 37.268,18.77 37.525,18.77 37.782,18.77 37.887,18.665 37.887,18.455 37.782,18.35 37.525,18.35 37.268,18.35 37.163,18.245 37.163,18.035 37.268,17.93 37.525,17.93 37.782,17.93 37.887,17.825 37.887,17.615 37.782,17.51 37.525,17.51 37.268,17.51 37.163,17.405 37.163,17.195 37.268,17.09 37.525,17.09 37.782,17.09 37.887,16.985 37.887,16.775 37.782,16.67 37.63,16.67 37.525,16.565 37.525,16.25 37.525,16.2 37.525,16.025 37.75,15.8 38.325,15.8 38.79,15.335 38.79,14.69 38.485,14.385 38.016,14.385 37.79,14.159 37.79,13.385 U34.B3@38.175,13
HEXASPI1.IO0: U25.L13 U34.D3 | length 29.2
  Bottom Layer w0.1: U25.L13@40.5,30.85 41,30.35 41,28.975 41.063,28.913 41.063,28.112
  Bottom Layer w0.12: U34.D3@40.175,13 39.79,12.615 39.79,10.785 40.25,10.325 42.65,10.325 45.55,13.225 45.55,22.9 45.05,23.4 45.05,24.125 41.063,28.112
HEXASPI1.IO1: U25.L14 U34.D2 | length 27.7
  Bottom Layer w0.1: 40.25,27.5 40.25,29 40.2,29.05 40.2,29.75 U25.L14@40.5,30.05
  Bottom Layer w0.12: U34.D2@40.175,14 40.637,13.538 40.637,12.813 40.85,12.6 42.575,12.6 43.45,13.475 43.45,18.325 43.45,18.52 43.555,18.625 43.609,18.625 43.714,18.73 43.714,18.94 43.609,19.045 43.45,19.045 43.266,19.045 43.161,19.15 43.161,19.36 43.266,19.465 43.45,19.465 43.609,19.465 43.714,19.57 43.714,19.78 43.609,19.885 43.45,19.885 43.266,19.885 43.161,19.99 43.161,20.2 43.266,20.305 43.45,20.305 43.609,20.305 43.714,20.41 43.714,20.62 43.609,20.725 43.45,20.725 43.266,20.725 43.161,20.83 43.161,21.04 43.266,21.145 43.45,21.145 43.609,21.145 43.714,21.25 43.714,21.46 43.609,21.565 43.45,21.565 43.266,21.565 43.161,21.67 43.161,21.88 43.266,21.985 43.45,21.985 43.609,21.985 43.714,22.09 43.714,22.3 43.609,22.405 43.45,22.405 43.266,22.405 43.161,22.51 43.161,22.72 43.266,22.825 43.45,22.825 43.609,22.825 43.714,22.93 43.714,23.14 43.609,23.245 43.45,23.245 43.266,23.245 43.161,23.35 43.161,23.56 43.266,23.665 43.345,23.665 43.45,23.77 43.45,23.875 43.45,24.3 40.25,27.5
HEXASPI1.IO2: U25.M15 U34.C4 | length 27.8
  Bottom Layer w0.1: 41.3,28.35 U25.M15@41.3,29.25
  Bottom Layer w0.12: U34.C4@39.175,12 39.57,11.605 39.57,10.48 40.025,10.025 43.075,10.025 45.725,12.675 45.725,12.8 46.025,13.1 46.025,23.1 45.475,23.65 45.475,24.175 41.3,28.35
HEXASPI1.IO3: U25.L15 U34.D4 | length 27
  Bottom Layer w0.1: 40.5,27.725 U25.L15@40.5,29.25
  Bottom Layer w0.12: U34.D4@40.175,12 40.56,11.615 42.515,11.615 44.15,13.25 44.15,13.46 44.15,13.795 44.065,13.88 43.96,13.985 43.96,14.195 44.065,14.3 44.15,14.3 44.488,14.3 44.593,14.405 44.593,14.615 44.488,14.72 44.15,14.72 44.112,14.72 44.007,14.825 44.007,15.035 44.112,15.14 44.15,15.14 44.488,15.14 44.593,15.245 44.593,15.455 44.488,15.56 44.15,15.56 44.112,15.56 44.007,15.665 44.007,15.875 44.112,15.98 44.15,15.98 44.488,15.98 44.593,16.085 44.593,16.295 44.488,16.4 44.15,16.4 44.112,16.4 44.007,16.505 44.007,16.715 44.112,16.82 44.15,16.82 44.488,16.82 44.593,16.925 44.593,17.135 44.488,17.24 44.15,17.24 44.112,17.24 44.007,17.345 44.007,17.555 44.112,17.66 44.15,17.66 44.488,17.66 44.593,17.765 44.593,17.975 44.488,18.08 44.22,18.08 44.15,18.15 44.15,24.075 40.5,27.725
HEXASPI1.IO4: U25.K13 U34.D5 | length 28
  Bottom Layer w0.1: U25.K13@39.7,30.85 40.2,30.35 40.624,30.35 40.8,30.174 40.8,27.9
  Bottom Layer w0.12: U34.D5@40.175,11 40.56,11.385 43.035,11.385 45.05,13.4 45.05,18.5 45.05,18.555 44.945,18.66 44.75,18.66 44.645,18.765 44.645,18.975 44.75,19.08 44.945,19.08 45.05,19.185 45.05,19.395 44.945,19.5 44.75,19.5 44.645,19.605 44.645,19.815 44.75,19.92 44.945,19.92 45.05,20.025 45.05,20.235 44.945,20.34 44.75,20.34 44.645,20.445 44.645,20.655 44.75,20.76 44.945,20.76 45.05,20.865 45.05,21.075 44.945,21.18 44.75,21.18 44.645,21.285 44.645,21.495 44.75,21.6 44.945,21.6 45.05,21.705 45.05,22.02 45.05,22.44 45.05,22.65 44.575,23.125 44.575,24.125 40.8,27.9
HEXASPI1.IO5: U25.K14 U34.E3 | length 27.9
  Bottom Layer w0.1: U25.K14@39.7,30.05 40,29.75 40,27.275
  Bottom Layer w0.12: 40,27.275 42.725,24.55 42.725,18.175 42.725,18.07 42.62,17.965 42.378,17.965 42.273,17.86 42.273,17.65 42.378,17.545 42.725,17.545 42.954,17.545 43.059,17.44 43.059,17.23 42.954,17.125 42.725,17.125 42.06,17.125 41.955,17.02 41.955,16.81 42.06,16.705 42.725,16.705 42.954,16.705 43.059,16.6 43.059,16.39 42.954,16.285 42.725,16.285 42.06,16.285 41.955,16.18 41.955,15.97 42.06,15.865 42.725,15.865 42.954,15.865 43.059,15.76 43.059,15.55 42.954,15.445 42.725,15.445 42.06,15.445 41.955,15.34 41.955,15.13 42.06,15.025 42.725,15.025 42.954,15.025 43.059,14.92 43.059,14.71 42.954,14.605 42.725,14.605 42.06,14.605 41.955,14.5 41.955,14.29 42.06,14.185 42.62,14.185 42.725,14.08 42.725,14 42.725,13.85 41.875,13 U34.E3@41.175,13
HEXASPI1.IO6: U25.K15 U34.E2 | length 27.1
  Bottom Layer w0.1: 39.7,26.975 U25.K15@39.7,29.25
  Bottom Layer w0.12: 39.7,26.975 41.575,25.1 41.575,24.9 41.575,24.69 41.51,24.625 41.51,24.335 41.575,24.27 42.278,24.27 42.383,24.165 42.383,23.955 42.278,23.85 41.575,23.85 41.51,23.785 41.51,23.495 41.575,23.43 42.278,23.43 42.383,23.325 42.383,23.115 42.278,23.01 41.575,23.01 41.51,22.945 41.51,22.655 41.575,22.59 42.278,22.59 42.383,22.485 42.383,22.275 42.278,22.17 41.575,22.17 41.51,22.105 41.51,21.815 41.575,21.75 42.278,21.75 42.383,21.645 42.383,21.435 42.278,21.33 41.575,21.33 41.51,21.265 41.51,20.975 41.575,20.91 42.278,20.91 42.383,20.805 42.383,20.595 42.278,20.49 41.575,20.49 41.51,20.425 41.51,20.135 41.575,20.07 42.278,20.07 42.383,19.965 42.383,19.755 42.278,19.65 41.575,19.65 41.51,19.585 41.51,19.295 41.575,19.23 42.278,19.23 42.383,19.125 42.383,18.915 42.278,18.81 41.575,18.81 41.51,18.745 41.51,18.455 41.575,18.39 41.575,18.075 41.575,14.4 U34.E2@41.175,14
HEXASPI1.IO7: U25.J12 U34.E1 | length 28.1
  Bottom Layer w0.1: U25.J12@38.9,31.65 39.4,31.15 39.4,29.926 39.4,29.374 39.4,28.15
  Bottom Layer w0.12: 39.4,28.15 39.4,26.775 40.825,25.35 40.825,25.025 40.825,24.92 40.72,24.815 40.59,24.815 40.485,24.71 40.485,24.5 40.59,24.395 40.825,24.395 41.06,24.395 41.165,24.29 41.165,24.08 41.06,23.975 40.825,23.975 40.59,23.975 40.485,23.87 40.485,23.66 40.59,23.555 40.825,23.555 41.06,23.555 41.165,23.45 41.165,23.24 41.06,23.135 40.825,23.135 40.59,23.135 40.485,23.03 40.485,22.82 40.59,22.715 40.825,22.715 41.06,22.715 41.165,22.61 41.165,22.4 41.06,22.295 40.825,22.295 40.59,22.295 40.485,22.19 40.485,21.98 40.59,21.875 40.825,21.875 41.06,21.875 41.165,21.77 41.165,21.56 41.06,21.455 40.825,21.455 40.59,21.455 40.485,21.35 40.485,21.14 40.59,21.035 40.825,21.035 41.06,21.035 41.165,20.93 41.165,20.72 41.06,20.615 40.825,20.615 40.59,20.615 40.485,20.51 40.485,20.3 40.59,20.195 40.825,20.195 41.06,20.195 41.165,20.09 41.165,19.88 41.06,19.775 40.825,19.775 40.59,19.775 40.485,19.67 40.485,19.46 40.59,19.355 40.825,19.355 41.06,19.355 41.165,19.25 41.165,19.04 41.06,18.935 40.825,18.935 40.59,18.935 40.485,18.83 40.485,18.62 40.59,18.515 40.825,18.515 41.06,18.515 41.165,18.41 41.165,18.2 41.06,18.095 40.825,18.095 40.59,18.095 40.485,17.99 40.485,17.78 40.59,17.675 40.825,17.675 41.06,17.675 41.165,17.57 41.165,17.36 41.06,17.255 40.825,17.255 40.59,17.255 40.485,17.15 40.485,16.94 40.59,16.835 40.72,16.835 40.825,16.73 40.825,16.2 40.825,16.125 41.175,15.775 U34.E1@41.175,15
HEXASPI1.IO8: U25.H12 U34.C2 | length 30.1
  Bottom Layer w0.1: 37.6,28.275 37.6,28.403 37.6,31.15 U25.H12@38.1,31.65
  Bottom Layer w0.12: 37.6,28.275 37.6,25.275 36.5,24.175 36.5,23.6 36.5,23.481 36.409,23.39 36.304,23.285 36.304,23.075 36.409,22.97 36.5,22.97 36.728,22.97 36.833,22.865 36.833,22.655 36.728,22.55 36.5,22.55 36.417,22.55 36.312,22.445 36.312,22.235 36.417,22.13 36.5,22.13 36.728,22.13 36.833,22.025 36.833,21.815 36.728,21.71 36.5,21.71 36.417,21.71 36.312,21.605 36.312,21.395 36.417,21.29 36.5,21.29 36.728,21.29 36.833,21.185 36.833,20.975 36.728,20.87 36.5,20.87 36.417,20.87 36.312,20.765 36.312,20.555 36.417,20.45 36.5,20.45 36.728,20.45 36.833,20.345 36.833,20.135 36.728,20.03 36.5,20.03 36.417,20.03 36.312,19.925 36.312,19.715 36.417,19.61 36.5,19.61 36.728,19.61 36.833,19.505 36.833,19.295 36.728,19.19 36.5,19.19 36.417,19.19 36.312,19.085 36.312,18.875 36.417,18.77 36.5,18.77 36.728,18.77 36.833,18.665 36.833,18.455 36.728,18.35 36.5,18.35 36.417,18.35 36.312,18.245 36.312,18.035 36.417,17.93 36.5,17.93 36.728,17.93 36.833,17.825 36.833,17.615 36.728,17.51 36.605,17.51 36.5,17.405 36.5,16.55 36.5,15.625 36.74,15.385 38.334,15.385 38.56,15.159 38.56,14.841 38.334,14.615 37.875,14.615 37.57,14.31 37.57,12.805 37.8,12.575 38.45,12.575 38.725,12.85 38.725,13.55 U34.C2@39.175,14
HEXASPI1.IO9: U25.G15 U34.B1 | length 28
  Bottom Layer w0.1: 37.3,25.575 U25.G15@37.3,29.25
  Bottom Layer w0.12: 37.3,25.575 35.475,23.75 35.475,23.5 35.475,23.395 35.37,23.29 35.288,23.29 35.183,23.185 35.183,22.975 35.288,22.87 35.475,22.87 35.833,22.87 35.938,22.765 35.938,22.555 35.833,22.45 35.475,22.45 35.288,22.45 35.183,22.345 35.183,22.135 35.288,22.03 35.475,22.03 35.833,22.03 35.938,21.925 35.938,21.715 35.833,21.61 35.475,21.61 35.288,21.61 35.183,21.505 35.183,21.295 35.288,21.19 35.475,21.19 35.833,21.19 35.938,21.085 35.938,20.875 35.833,20.77 35.475,20.77 35.288,20.77 35.183,20.665 35.183,20.455 35.288,20.35 35.475,20.35 35.833,20.35 35.938,20.245 35.938,20.035 35.833,19.93 35.475,19.93 35.288,19.93 35.183,19.825 35.183,19.615 35.288,19.51 35.475,19.51 35.833,19.51 35.938,19.405 35.938,19.195 35.833,19.09 35.475,19.09 35.288,19.09 35.183,18.985 35.183,18.775 35.288,18.67 35.475,18.67 35.833,18.67 35.938,18.565 35.938,18.355 35.833,18.25 35.475,18.25 35.288,18.25 35.183,18.145 35.183,17.935 35.288,17.83 35.475,17.83 35.833,17.83 35.938,17.725 35.938,17.515 35.833,17.41 35.475,17.41 35.288,17.41 35.183,17.305 35.183,17.095 35.288,16.99 35.475,16.99 35.833,16.99 35.938,16.885 35.938,16.675 35.833,16.57 35.475,16.57 35.288,16.57 35.183,16.465 35.183,16.255 35.288,16.15 35.37,16.15 35.475,16.045 35.475,15.85 35.475,15.325 35.8,15 U34.B1@38.175,15
HEXASPI1.IO10: U25.G14 U34.A2 | length 28.8
  Bottom Layer w0.1: 36.888,25.813 37.025,25.95 37.025,29 37,29.025 37,29.126 37,29.374 37,29.75 U25.G14@37.3,30.05
  Bottom Layer w0.12: 36.888,25.813 34.8,23.725 34.8,14.775 34.8,14.245 34.695,14.14 34.525,14.14 34.42,14.035 34.42,13.825 34.525,13.72 34.695,13.72 34.8,13.615 34.8,13.405 34.695,13.3 34.525,13.3 34.42,13.195 34.42,12.985 34.525,12.88 34.695,12.88 34.8,12.775 34.8,12.46 34.8,12.25 34.925,12.125 35.225,12.125 35.3,12.2 35.3,14.525 35.425,14.65 35.625,14.65 35.75,14.525 35.75,12.2 35.825,12.125 36.1,12.125 36.225,12.25 36.225,13.85 36.375,14 U34.A2@37.175,14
